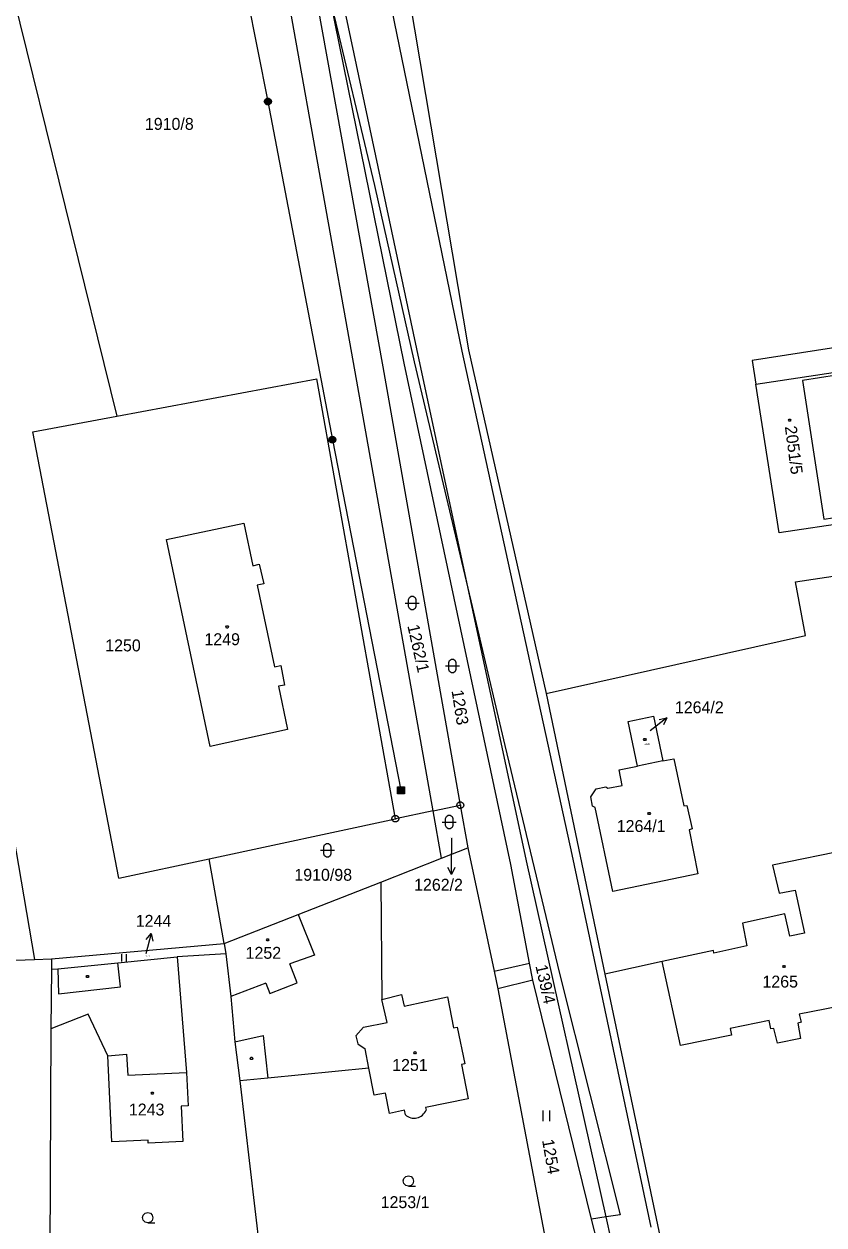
# Model space of a CAD drawing. Extents: x -609861 to -605046, y -1120287 to -1116307.
# Drawn here: x -607191.9 to -607078, y -1118914.2 to -1118743 of the extents above; entities that cross this region are included whole.
import ezdxf

# ---------------------------------------------------------------- set-up
doc = ezdxf.new("R2010")
doc.units = 0
for name, color, linetype in [('Vrstva 1', 7, 'Continuous'), ('Vrstva 2', 7, 'Continuous'), ('Vrstva 3', 7, 'Continuous'), ('Vrstva 4', 7, 'Continuous'), ('Vrstva 5', 7, 'Continuous'), ('Vrstva 6', 7, 'Continuous'), ('Vrstva 7', 7, 'Continuous'), ('Vrstva 8', 7, 'Continuous')]:
    doc.layers.add(name, color=color, linetype=linetype)

msp = doc.modelspace()

# ---------------------------------------------------------------- linework, layer by layer
at = {"layer": 'Vrstva 1'}
for p, q in [((-607195.67, -1118730.14), (-607178.69, -1118798.88)), ((-607137.33, -1118737.79), (-607128.61, -1118789.42)), ((-607150.14, -1118740.32), (-607140.81, -1118791.87)), ((-607148.23, -1118739.89), (-607142.03, -1118766.04)), ((-607137.8, -1118791.32), (-607148.23, -1118739.89)), ((-607144.75, -1118792.59), (-607153.98, -1118741.08)), ((-607142.03, -1118766.04), (-607136.37, -1118791.15)), ((-607071.88, -1118788.43), (-607088.24, -1118790.97)), ((-607128.61, -1118789.42), (-607117.57, -1118838.43)), ((-607140.81, -1118791.87), (-607129.8, -1118854.32)), ((-607122.59, -1118862.79), (-607137.8, -1118791.32)), ((-607136.37, -1118791.15), (-607128.31, -1118825.19)), ((-607088.24, -1118790.97), (-607087.71, -1118794.35)), ((-607178.69, -1118798.88), (-607150.23, -1118793.59)), ((-607139.03, -1118856.26), (-607150.23, -1118793.59)), ((-607133.65, -1118855.13), (-607144.75, -1118792.59)), ((-607084.41, -1118815.53), (-607087.71, -1118794.35)), ((-607190.66, -1118801.1), (-607178.69, -1118798.88)), ((-607203.13, -1118802.05), (-607190.42, -1118876.31)), ((-607178.44, -1118864.73), (-607190.66, -1118801.1)), ((-607171.63, -1118816.47), (-607160.63, -1118814.13)), ((-607160.63, -1118814.13), (-607159.34, -1118820.2)), ((-607071.78, -1118813.65), (-607084.41, -1118815.53)), ((-607165.4, -1118845.97), (-607171.63, -1118816.47)), ((-607159.34, -1118820.2), (-607158.43, -1118819.99)), ((-607158.43, -1118819.99), (-607157.79, -1118822.77)), ((-607082.07, -1118822.51), (-607064.95, -1118819.93)), ((-607157.79, -1118822.77), (-607158.72, -1118822.97)), ((-607080.63, -1118830.13), (-607082.07, -1118822.51)), ((-607158.72, -1118822.97), (-607156.23, -1118834.59)), ((-607128.31, -1118825.19), (-607123.43, -1118845.8)), ((-607117.57, -1118838.43), (-607080.63, -1118830.13)), ((-607156.23, -1118834.59), (-607155.37, -1118834.43)), ((-607155.37, -1118834.43), (-607154.81, -1118837.21)), ((-607154.81, -1118837.21), (-607155.68, -1118837.38)), ((-607155.68, -1118837.38), (-607154.39, -1118843.53)), ((-607117.57, -1118838.43), (-607109.19, -1118878.4)), ((-607105.89, -1118842.38), (-607102.29, -1118841.64)), ((-607102.29, -1118841.64), (-607100.97, -1118848.03)), ((-607104.58, -1118848.77), (-607105.89, -1118842.38)), ((-607154.39, -1118843.53), (-607165.4, -1118845.97)), ((-607123.43, -1118845.8), (-607115.65, -1118878.33)), ((-607100.97, -1118848.03), (-607104.58, -1118848.77)), ((-607133.65, -1118855.13), (-607139.03, -1118856.26)), ((-607133.65, -1118855.13), (-607129.8, -1118854.32)), ((-607132.45, -1118861.88), (-607133.65, -1118855.13)), ((-607129.8, -1118854.32), (-607128.73, -1118860.42)), ((-607165.56, -1118861.96), (-607139.03, -1118856.26)), ((-607132.45, -1118861.88), (-607128.73, -1118860.42)), ((-607128.73, -1118860.42), (-607124.96, -1118877.96)), ((-607072.98, -1118860.36), (-607085.36, -1118862.89)), ((-607178.44, -1118864.73), (-607165.56, -1118861.96)), ((-607163.4, -1118874.06), (-607165.56, -1118861.96)), ((-607141.11, -1118865.28), (-607132.45, -1118861.88)), ((-607119.96, -1118876.86), (-607122.59, -1118862.79)), ((-607085.36, -1118862.89), (-607084.4, -1118866.87)), ((-607152.86, -1118869.9), (-607141.11, -1118865.28)), ((-607141.11, -1118865.28), (-607140.96, -1118882)), ((-607084.4, -1118866.87), (-607082.11, -1118866.43)), ((-607082.11, -1118866.43), (-607080.8, -1118872.59)), ((-607163.4, -1118874.06), (-607152.86, -1118869.9)), ((-607083.58, -1118869.81), (-607089.63, -1118871.14)), ((-607082.88, -1118872.99), (-607083.58, -1118869.81)), ((-607089.63, -1118871.14), (-607088.98, -1118874.38)), ((-607188.02, -1118876.22), (-607163.4, -1118874.06)), ((-607163.4, -1118874.06), (-607163.2, -1118875.53)), ((-607080.8, -1118872.59), (-607082.88, -1118872.99)), ((-607163.2, -1118875.53), (-607170.13, -1118875.93)), ((-607163.2, -1118875.53), (-607162.46, -1118881.57)), ((-607093.76, -1118875.02), (-607101.07, -1118876.62)), ((-607093.68, -1118875.42), (-607093.76, -1118875.02)), ((-607088.98, -1118874.38), (-607093.68, -1118875.42)), ((-607213.83, -1118877.15), (-607190.42, -1118876.31)), ((-607190.42, -1118876.31), (-607188.02, -1118876.22)), ((-607188.02, -1118876.22), (-607188.03, -1118877.72)), ((-607187.11, -1118877.67), (-607178.55, -1118876.79)), ((-607178.55, -1118876.79), (-607170.13, -1118875.93)), ((-607170.13, -1118875.93), (-607168.78, -1118892.42)), ((-607124.96, -1118877.96), (-607119.96, -1118876.86)), ((-607119.47, -1118879.27), (-607119.96, -1118876.86)), ((-607101.07, -1118876.62), (-607109.19, -1118878.4)), ((-607098.45, -1118888.58), (-607101.07, -1118876.62)), ((-607188.03, -1118877.72), (-607188.08, -1118886.22)), ((-607188.03, -1118877.72), (-607187.11, -1118877.67)), ((-607119.47, -1118879.27), (-607124.44, -1118880.49)), ((-607111.09, -1118913.32), (-607119.47, -1118879.27)), ((-607115.65, -1118878.33), (-607107.04, -1118912.71)), ((-607109.19, -1118878.4), (-607100.61, -1118919.35)), ((-607124.44, -1118880.49), (-607117.52, -1118917.07)), ((-607162.46, -1118881.57), (-607161.9, -1118888.03)), ((-607140.96, -1118882), (-607138.19, -1118881.33)), ((-607140.23, -1118885.32), (-607140.96, -1118882)), ((-607138.19, -1118881.33), (-607137.8, -1118882.95)), ((-607137.8, -1118882.95), (-607131.64, -1118881.64)), ((-607131.64, -1118881.64), (-607130.74, -1118886.07)), ((-607182.79, -1118884.1), (-607188.08, -1118886.22)), ((-607179.98, -1118890.06), (-607182.79, -1118884.1)), ((-607075.92, -1118883.03), (-607081.52, -1118884.1)), ((-607081.52, -1118884.1), (-607081.27, -1118885.27)), ((-607143.56, -1118885.97), (-607144.69, -1118887.21)), ((-607143.56, -1118885.97), (-607140.23, -1118885.32)), ((-607130.74, -1118886.07), (-607130.24, -1118885.96)), ((-607130.24, -1118885.96), (-607129.13, -1118891.17)), ((-607085.83, -1118885.03), (-607091.39, -1118886.16)), ((-607085.58, -1118886.2), (-607085.83, -1118885.03)), ((-607085.13, -1118886.13), (-607085.58, -1118886.2)), ((-607084.62, -1118888.26), (-607085.13, -1118886.13)), ((-607081.27, -1118885.27), (-607081.75, -1118885.38)), ((-607081.75, -1118885.38), (-607081.35, -1118887.59)), ((-607188.08, -1118886.22), (-607188.27, -1118918.34)), ((-607144.69, -1118887.21), (-607144.39, -1118888.34)), ((-607091.18, -1118887.11), (-607098.45, -1118888.58)), ((-607091.39, -1118886.16), (-607091.18, -1118887.11)), ((-607081.35, -1118887.59), (-607084.62, -1118888.26)), ((-607161.9, -1118888.03), (-607161.19, -1118893.61)), ((-607144.39, -1118888.34), (-607143.36, -1118889.04)), ((-607142.81, -1118891.8), (-607143.36, -1118889.04)), ((-607179.42, -1118902.3), (-607179.98, -1118890.06)), ((-607129.13, -1118891.17), (-607129.64, -1118891.27)), ((-607129.64, -1118891.27), (-607128.66, -1118896.19)), ((-607168.78, -1118892.42), (-607168.56, -1118897.19)), ((-607142.81, -1118891.8), (-607157.22, -1118893.22)), ((-607142.04, -1118895.64), (-607142.81, -1118891.8)), ((-607157.22, -1118893.22), (-607161.19, -1118893.61)), ((-607161.19, -1118893.61), (-607158.35, -1118917.94)), ((-607140.43, -1118895.35), (-607142.04, -1118895.64)), ((-607139.86, -1118898.26), (-607140.43, -1118895.35)), ((-607128.66, -1118896.19), (-607134.75, -1118897.41)), ((-607168.56, -1118897.19), (-607169.56, -1118897.23)), ((-607169.56, -1118897.23), (-607169.3, -1118902.26)), ((-607137.75, -1118897.77), (-607139.86, -1118898.26)), ((-607137.62, -1118898.44), (-607137.75, -1118897.77)), ((-607134.75, -1118897.41), (-607134.67, -1118897.77)), ((-607174.24, -1118902.07), (-607179.42, -1118902.3)), ((-607174.22, -1118902.48), (-607174.24, -1118902.07)), ((-607169.3, -1118902.26), (-607174.22, -1118902.48)), ((-607109.02, -1118913.01), (-607111.09, -1118913.32)), ((-607110.23, -1118916.83), (-607111.09, -1118913.32)), ((-607107.04, -1118912.71), (-607109.02, -1118913.01))]:
    msp.add_line(p, q, dxfattribs=at)
msp.add_arc((-607136.372, -1118897.104), 1.828, 226.96551, 338.62623, dxfattribs=at)
at = {"layer": 'Vrstva 3'}
for p, q in [((-607178.03, -1118875.56), (-607178.03, -1118876.61)), ((-607177.33, -1118876.61), (-607177.33, -1118875.56)), ((-607118.03, -1118897.84), (-607118.03, -1118899.34)), ((-607117.03, -1118899.34), (-607117.03, -1118897.84))]:
    msp.add_line(p, q, dxfattribs=at)
for points in [[(-607137.65, -1118825.53), (-607136.38, -1118825.53), (-607135.65, -1118825.53)], [(-607131.92, -1118834.49), (-607130.65, -1118834.49), (-607129.92, -1118834.49)], [(-607132.38, -1118856.73), (-607131.11, -1118856.73), (-607130.38, -1118856.73)], [(-607149.72, -1118860.75), (-607148.45, -1118860.75), (-607147.72, -1118860.75)], [(-607137.17, -1118908.62), (-607137.55, -1118908.52), (-607137.82, -1118908.25), (-607137.92, -1118907.88), (-607137.82, -1118907.51), (-607137.55, -1118907.24), (-607137.18, -1118907.14), (-607136.81, -1118907.24), (-607136.54, -1118907.51), (-607136.44, -1118907.89), (-607136.54, -1118908.27), (-607136.81, -1118908.54), (-607137.19, -1118908.64), (-607136.19, -1118908.64)], [(-607174.29, -1118913.85), (-607174.67, -1118913.75), (-607174.94, -1118913.48), (-607175.04, -1118913.11), (-607174.94, -1118912.74), (-607174.67, -1118912.47), (-607174.3, -1118912.37), (-607173.93, -1118912.47), (-607173.66, -1118912.74), (-607173.56, -1118913.12), (-607173.66, -1118913.5), (-607173.93, -1118913.77), (-607174.31, -1118913.87), (-607173.31, -1118913.87)]]:
    msp.add_lwpolyline(points, dxfattribs=at)
for points in [[(-607137.15, -1118825.03), (-607137.05, -1118824.74), (-607136.8, -1118824.56), (-607136.49, -1118824.56), (-607136.24, -1118824.74), (-607136.14, -1118825.03), (-607136.14, -1118826.03), (-607136.24, -1118826.32), (-607136.49, -1118826.5), (-607136.8, -1118826.5), (-607137.05, -1118826.32), (-607137.15, -1118826.03)], [(-607131.42, -1118833.99), (-607131.32, -1118833.7), (-607131.07, -1118833.52), (-607130.76, -1118833.52), (-607130.51, -1118833.7), (-607130.41, -1118833.99), (-607130.41, -1118834.99), (-607130.51, -1118835.28), (-607130.76, -1118835.46), (-607131.07, -1118835.46), (-607131.32, -1118835.28), (-607131.42, -1118834.99)], [(-607131.88, -1118856.23), (-607131.78, -1118855.94), (-607131.53, -1118855.76), (-607131.22, -1118855.76), (-607130.97, -1118855.94), (-607130.87, -1118856.23), (-607130.87, -1118857.23), (-607130.97, -1118857.52), (-607131.22, -1118857.7), (-607131.53, -1118857.7), (-607131.78, -1118857.52), (-607131.88, -1118857.23)], [(-607149.22, -1118860.25), (-607149.12, -1118859.96), (-607148.87, -1118859.78), (-607148.56, -1118859.78), (-607148.31, -1118859.96), (-607148.21, -1118860.25), (-607148.21, -1118861.25), (-607148.31, -1118861.54), (-607148.56, -1118861.72), (-607148.87, -1118861.72), (-607149.12, -1118861.54), (-607149.22, -1118861.25)]]:
    msp.add_lwpolyline(points, close=True, dxfattribs=at)
at = {"layer": 'Vrstva 4'}
for p, q in [((-607139.98, -1118738.84), (-607129.59, -1118789.62)), ((-607135.65, -1118790.87), (-607146.51, -1118739.65)), ((-607129.59, -1118789.62), (-607113.89, -1118861.35)), ((-607128.31, -1118825.19), (-607135.65, -1118790.87)), ((-607087.71, -1118794.35), (-607071.25, -1118791.84)), ((-607076.21, -1118793.05), (-607081.06, -1118793.79)), ((-607081.06, -1118793.79), (-607078.05, -1118813.59)), ((-607078.05, -1118813.59), (-607073.11, -1118812.83)), ((-607120.38, -1118862.27), (-607128.31, -1118825.19)), ((-607100.97, -1118848.03), (-607099.41, -1118847.71)), ((-607099.41, -1118847.71), (-607097.95, -1118854.44)), ((-607107.16, -1118849.3), (-607104.58, -1118848.77)), ((-607106.75, -1118851.54), (-607107.16, -1118849.3)), ((-607110.47, -1118852.01), (-607109.09, -1118851.73)), ((-607109.09, -1118851.73), (-607108.79, -1118851.9)), ((-607108.79, -1118851.9), (-607106.75, -1118851.54)), ((-607111.22, -1118853.12), (-607110.47, -1118852.01)), ((-607110.96, -1118854.45), (-607111.22, -1118853.12)), ((-607110.6, -1118854.65), (-607110.96, -1118854.45)), ((-607108.07, -1118866.63), (-607110.6, -1118854.65)), ((-607097.95, -1118854.44), (-607097.53, -1118854.35)), ((-607097.53, -1118854.35), (-607096.79, -1118857.72)), ((-607096.79, -1118857.72), (-607097.21, -1118857.82)), ((-607097.21, -1118857.82), (-607095.96, -1118864.12)), ((-607113.89, -1118861.35), (-607102.64, -1118914.48)), ((-607109.02, -1118913.01), (-607120.38, -1118862.27)), ((-607095.96, -1118864.12), (-607108.07, -1118866.63)), ((-607152.86, -1118869.9), (-607150.54, -1118875.69)), ((-607150.54, -1118875.69), (-607154.06, -1118876.96)), ((-607178.2, -1118880.21), (-607178.55, -1118876.79)), ((-607187.11, -1118877.67), (-607187.01, -1118881.22)), ((-607124.96, -1118877.96), (-607124.44, -1118880.49)), ((-607187.01, -1118881.22), (-607178.2, -1118880.21)), ((-607157.48, -1118879.67), (-607162.46, -1118881.57)), ((-607161.9, -1118888.03), (-607157.85, -1118887.17)), ((-607157.85, -1118887.17), (-607157.22, -1118893.22)), ((-607179.98, -1118890.06), (-607177.33, -1118889.81)), ((-607177.33, -1118889.81), (-607177.13, -1118892.81)), ((-607177.13, -1118892.81), (-607168.78, -1118892.42)), ((-607108.3, -1118916.23), (-607109.02, -1118913.01))]:
    msp.add_line(p, q, dxfattribs=at)
msp.add_lwpolyline([(-607157.48, -1118879.67), (-607156.91, -1118881.15), (-607153.02, -1118879.65), (-607154.06, -1118876.96)], dxfattribs=at)
at = {"layer": 'Vrstva 5'}
for points in [[(-607082.8, -1118799.31), (-607082.71, -1118799.46), (-607082.8, -1118799.61), (-607082.98, -1118799.61), (-607083.07, -1118799.46), (-607082.98, -1118799.31)], [(-607162.89, -1118828.78), (-607162.8, -1118828.93), (-607162.89, -1118829.08), (-607163.07, -1118829.08), (-607163.16, -1118828.93), (-607163.07, -1118828.78)], [(-607103.42, -1118844.82), (-607103.33, -1118844.97), (-607103.42, -1118845.12), (-607103.6, -1118845.12), (-607103.69, -1118844.97), (-607103.6, -1118844.82)], [(-607102.81, -1118855.37), (-607102.72, -1118855.52), (-607102.81, -1118855.67), (-607102.99, -1118855.67), (-607103.08, -1118855.52), (-607102.99, -1118855.37)], [(-607157.14, -1118873.37), (-607157.05, -1118873.52), (-607157.14, -1118873.67), (-607157.32, -1118873.67), (-607157.41, -1118873.52), (-607157.32, -1118873.37)], [(-607083.61, -1118877.17), (-607083.52, -1118877.32), (-607083.61, -1118877.47), (-607083.79, -1118877.47), (-607083.88, -1118877.32), (-607083.79, -1118877.17)], [(-607182.78, -1118878.6), (-607182.69, -1118878.75), (-607182.78, -1118878.9), (-607182.96, -1118878.9), (-607183.05, -1118878.75), (-607182.96, -1118878.6)], [(-607136.16, -1118889.45), (-607136.07, -1118889.6), (-607136.16, -1118889.75), (-607136.34, -1118889.75), (-607136.43, -1118889.6), (-607136.34, -1118889.45)], [(-607159.44, -1118890.26), (-607159.35, -1118890.41), (-607159.44, -1118890.56), (-607159.62, -1118890.56), (-607159.71, -1118890.41), (-607159.62, -1118890.26)], [(-607173.56, -1118895.22), (-607173.47, -1118895.37), (-607173.56, -1118895.52), (-607173.74, -1118895.52), (-607173.83, -1118895.37), (-607173.74, -1118895.22)]]:
    msp.add_lwpolyline(points, close=True, dxfattribs=at)
at = {"layer": 'Vrstva 6'}
for p, q in [((-607167.85, -1118700.44), (-607157.2, -1118754.07)), ((-607157.2, -1118754.07), (-607148.01, -1118802.25)), ((-607148.01, -1118802.25), (-607138.26, -1118852.21))]:
    msp.add_line(p, q, dxfattribs=at)
for points in [[(-607157.35, -1118753.59), (-607157.04, -1118753.59), (-607156.79, -1118753.77), (-607156.69, -1118754.06), (-607156.79, -1118754.35), (-607157.04, -1118754.53), (-607157.35, -1118754.53), (-607157.6, -1118754.35), (-607157.7, -1118754.06), (-607157.6, -1118753.77), (-607157.35, -1118753.59), (-607157.32, -1118753.63), (-607157.08, -1118753.63), (-607156.92, -1118753.71), (-607157.48, -1118753.71), (-607157.56, -1118753.79), (-607156.84, -1118753.79), (-607156.84, -1118753.87), (-607157.56, -1118753.87), (-607157.6, -1118753.95), (-607156.8, -1118753.95), (-607156.76, -1118754.03), (-607157.64, -1118754.03), (-607157.64, -1118754.11), (-607156.76, -1118754.11), (-607156.79, -1118754.19), (-607157.6, -1118754.19), (-607157.59, -1118754.27), (-607156.78, -1118754.27), (-607156.83, -1118754.35), (-607157.55, -1118754.35), (-607157.47, -1118754.43), (-607156.91, -1118754.43), (-607157.02, -1118754.51), (-607157.36, -1118754.51)], [(-607148.16, -1118801.77), (-607147.85, -1118801.77), (-607147.6, -1118801.95), (-607147.5, -1118802.24), (-607147.6, -1118802.53), (-607147.85, -1118802.71), (-607148.16, -1118802.71), (-607148.41, -1118802.53), (-607148.51, -1118802.24), (-607148.41, -1118801.95), (-607148.16, -1118801.77), (-607148.13, -1118801.81), (-607147.89, -1118801.81), (-607147.73, -1118801.89), (-607148.29, -1118801.89), (-607148.37, -1118801.97), (-607147.65, -1118801.97), (-607147.65, -1118802.05), (-607148.37, -1118802.05), (-607148.41, -1118802.13), (-607147.61, -1118802.13), (-607147.57, -1118802.21), (-607148.45, -1118802.21), (-607148.45, -1118802.29), (-607147.57, -1118802.29), (-607147.6, -1118802.37), (-607148.41, -1118802.37), (-607148.4, -1118802.45), (-607147.59, -1118802.45), (-607147.64, -1118802.53), (-607148.36, -1118802.53), (-607148.28, -1118802.61), (-607147.72, -1118802.61), (-607147.83, -1118802.69), (-607148.17, -1118802.69)], [(-607138.76, -1118851.71), (-607137.76, -1118851.71), (-607137.76, -1118852.71), (-607138.76, -1118852.71), (-607138.76, -1118851.71), (-607138.7, -1118851.77), (-607137.82, -1118851.77), (-607137.82, -1118851.85), (-607138.7, -1118851.85), (-607138.7, -1118851.93), (-607137.82, -1118851.93), (-607137.82, -1118852.01), (-607138.7, -1118852.01), (-607138.7, -1118852.09), (-607137.82, -1118852.09), (-607137.82, -1118852.17), (-607138.7, -1118852.17), (-607138.7, -1118852.25), (-607137.82, -1118852.25), (-607137.82, -1118852.33), (-607138.7, -1118852.33), (-607138.7, -1118852.41), (-607137.82, -1118852.41), (-607137.82, -1118852.49), (-607138.7, -1118852.49), (-607138.7, -1118852.57), (-607137.82, -1118852.57), (-607137.82, -1118852.65), (-607138.7, -1118852.65)]]:
    msp.add_lwpolyline(points, dxfattribs=at)
at = {"layer": 'Vrstva 7'}
for p, q in [((-607100.408, -1118841.862), (-607102.74, -1118843.75)), ((-607131.07, -1118859.04), (-607131.07, -1118861.21)), ((-607131.069, -1118864.21), (-607131.07, -1118861.21)), ((-607173.807, -1118872.624), (-607174.59, -1118875.52))]:
    msp.add_line(p, q, dxfattribs=at)
for points in [[(-607101.5, -1118842.103), (-607100.408, -1118841.862), (-607100.871, -1118842.88)], [(-607130.569, -1118863.21), (-607131.069, -1118864.21), (-607131.569, -1118863.21)], [(-607174.55, -1118873.459), (-607173.807, -1118872.624), (-607173.585, -1118873.72)]]:
    msp.add_lwpolyline(points, dxfattribs=at)
at = {"layer": 'Vrstva 8'}
for p, q in [((-607129.92, -1118854.32), (-607129.68, -1118854.32)), ((-607139.15, -1118856.26), (-607138.91, -1118856.26))]:
    msp.add_line(p, q, dxfattribs=at)
for points in [[(-607129.65, -1118853.84), (-607129.4, -1118854.02), (-607129.3, -1118854.31), (-607129.4, -1118854.6), (-607129.65, -1118854.78), (-607129.96, -1118854.78), (-607130.21, -1118854.6), (-607130.31, -1118854.31), (-607130.21, -1118854.02), (-607129.96, -1118853.84)], [(-607138.88, -1118855.78), (-607138.63, -1118855.96), (-607138.53, -1118856.25), (-607138.63, -1118856.54), (-607138.88, -1118856.72), (-607139.19, -1118856.72), (-607139.44, -1118856.54), (-607139.54, -1118856.25), (-607139.44, -1118855.96), (-607139.19, -1118855.78)]]:
    msp.add_lwpolyline(points, close=True, dxfattribs=at)

# ---------------------------------------------------------------- texts
at = {"layer": 'Vrstva 2'}
for s, height, p in [('1910/8', 1.7, (-607174.707, -1118758.09)), ('1250', 1.7, (-607180.357, -1118832.41)), ('1249', 1.7, (-607166.227, -1118831.53)), ('1264/2', 0.2, (-607103.614, -1118845.73)), ('1264/1', 1.7, (-607107.517, -1118858.15)), ('1262/2', 0.1, (-607131.305, -1118859.04)), ('1910/98', 1.7, (-607153.423, -1118865.1)), ('1244', 0.2, (-607174.674, -1118875.93)), ('1252', 1.7, (-607160.367, -1118876.22)), ('1265', 1.7, (-607086.767, -1118880.32)), ('1251', 1.7, (-607139.497, -1118892.2)), ('1243', 1.7, (-607176.987, -1118898.55)), ('1253/1', 1.7, (-607141.134, -1118911.75))]:
    msp.add_text(s, height=height, dxfattribs=at).set_placement(p)
for s, rotation, p in [('2051/5', 277.48346, (-607083.587, -1118800.385)), ('1262/1', 282.64008, (-607137.342, -1118828.773)), ('1263', 278.97315, (-607131.049, -1118838.018)), ('139/4', 282.58278, (-607119.104, -1118877.243)), ('1254', 279.88988, (-607118.163, -1118902.067))]:
    msp.add_text(s, height=1.7, rotation=rotation, dxfattribs=at).set_placement(p)
at = {"layer": 'Vrstva 7'}
for s, p in [('1264/2', (-607099.237, -1118841.23)), ('1262/2', (-607136.375, -1118866.52)), ('1244', (-607176.009, -1118871.66))]:
    msp.add_text(s, height=1.7, dxfattribs=at).set_placement(p)

doc.saveas('drawing.dxf')
